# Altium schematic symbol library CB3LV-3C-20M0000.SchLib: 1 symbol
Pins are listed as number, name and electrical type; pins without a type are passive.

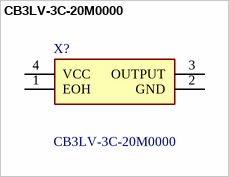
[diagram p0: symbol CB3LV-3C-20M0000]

## CB3LV-3C-20M0000
designator X?
Oscillator XO 20MHz +/-50ppm 50pF HCMOS/TTL 55% 3.3V 4-Pin SMD T/R; Manufacturer_Name: CTS; Geometry.Height: 1.8mm
footprint CB3LV3C20M0000
pins: 1 EOH, 2 GND, 3 OUTPUT, 4 VCC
